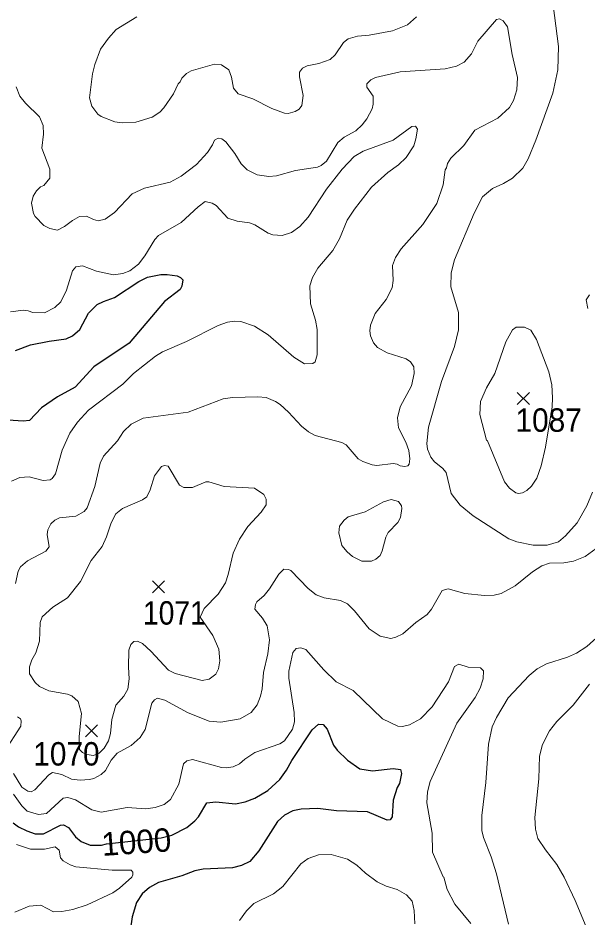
# Model space of a CAD drawing. Extents: x 265 to 291.4, y 7731.5 to 7759.6.
# Drawn here: x 276.962 to 278.902, y 7743.215 to 7746.284 of the extents above; entities that cross this region are included whole.
import ezdxf
from ezdxf.enums import TextEntityAlignment as Align

# ---------------------------------------------------------------- set-up
doc = ezdxf.new("R2010")
doc.units = 0
doc.header["$LTSCALE"] = 0.032
for name, color, linetype, lineweight in [('1', 7, 'Continuous', 25), ('2', 7, 'Continuous', 13), ('21', 7, 'Continuous', 25), ('61', 7, 'Continuous', 13)]:
    doc.layers.add(name, color=color, linetype=linetype, lineweight=lineweight)

msp = doc.modelspace()

# ---------------------------------------------------------------- linework, layer by layer
at = {"layer": '1'}
for points in [[(276.9536, 7745.1492), (277.0046, 7745.1675), (277.0682, 7745.181), (277.1255, 7745.189), (277.1477, 7745.1985), (277.1724, 7745.22), (277.2026, 7745.2765), (277.232, 7745.3051), (277.2535, 7745.3163), (277.2909, 7745.3298), (277.3737, 7745.3847), (277.4039, 7745.399), (277.4484, 7745.4086), (277.4707, 7745.4086), (277.5041, 7745.403), (277.516, 7745.3982), (277.524, 7745.3895), (277.5208, 7745.368), (277.5144, 7745.3569), (277.4612, 7745.3155), (277.341, 7745.1739), (277.2209, 7745.0927), (277.1565, 7745.0235), (277.0968, 7744.9909), (277.0419, 7744.9535), (277.0014, 7744.9098), (276.9791, 7744.9074), (276.9282, 7744.9106)], [(276.9457, 7743.536), (276.9632, 7743.5233), (276.9918, 7743.5089), (277.0205, 7743.4994), (277.0491, 7743.4994), (277.1071, 7743.5289), (277.1164, 7743.5296), (277.1343, 7743.5209), (277.1582, 7743.4884), (277.1772, 7743.4723), (277.2082, 7743.4604), (277.2464, 7743.4604), (277.2631, 7743.4644), (277.4494, 7743.485), (277.4859, 7743.4943), (277.5375, 7743.5209), (277.5646, 7743.5431), (277.5773, 7743.5575), (277.6059, 7743.6052), (277.6362, 7743.6076), (277.703, 7743.6012), (277.7364, 7743.6084), (277.7698, 7743.6203), (277.8135, 7743.6466), (277.8541, 7743.6847), (277.8772, 7743.7158), (277.8955, 7743.7492), (277.9647, 7743.8542), (277.9862, 7743.8733), (278.0021, 7743.8725), (278.0156, 7743.8566), (278.0371, 7743.8017), (278.0498, 7743.7842), (278.0848, 7743.75), (278.127, 7743.7205), (278.1707, 7743.7142), (278.2407, 7743.7221), (278.2662, 7743.7182), (278.2693, 7743.7046), (278.263, 7743.6704), (278.255, 7743.6569), (278.2415, 7743.614), (278.2375, 7743.5567), (278.2312, 7743.5463), (278.2208, 7743.5455), (278.1532, 7743.5742), (278.0482, 7743.5773), (277.9846, 7743.5853), (277.9273, 7743.5829), (277.8987, 7743.5773), (277.87, 7743.5622), (277.8462, 7743.5407), (277.7833, 7743.4405), (277.7523, 7743.4047), (277.7237, 7743.3912), (277.6934, 7743.3832)], [(277.6934, 7743.3832), (277.5932, 7743.3785), (277.5646, 7743.3721), (277.52, 7743.3554), (277.4405, 7743.3323), (277.4103, 7743.3156), (277.3848, 7743.2942)], [(277.3848, 7743.2942), (277.3657, 7743.264), (277.3514, 7743.2162), (277.3442, 7743.1685), (277.3323, 7743.1239), (277.3092, 7743.0889), (277.2909, 7743.077), (277.2368, 7743.0531), (277.2058, 7743.0332), (277.2002, 7743.0253), (277.1931, 7743.003), (277.1931, 7742.9927), (277.2137, 7742.9458), (277.2814, 7742.8503), (277.3354, 7742.7556), (277.3689, 7742.7174), (277.3562, 7742.6944), (277.3259, 7742.692), (277.283, 7742.6944), (277.143, 7742.7333), (277.0427, 7742.7556), (276.9998, 7742.762), (276.9711, 7742.7628), (276.9234, 7742.758)]]:
    msp.add_lwpolyline(points, dxfattribs=at)
at = {"layer": '2'}
for points in [[(278.4635, 7745.2193), (278.4635, 7745.2789), (278.4372, 7745.3656), (278.4388, 7745.4134), (278.4507, 7745.4579), (278.5168, 7745.617), (278.5462, 7745.6727), (278.5796, 7745.7021), (278.6178, 7745.7188), (278.648, 7745.7363), (278.683, 7745.7713), (278.7013, 7745.8031), (278.7276, 7745.8668), (278.7856, 7746.0275), (278.8031, 7746.107), (278.8047, 7746.1866), (278.7817, 7746.3632)], [(278.3211, 7746.2876), (278.2901, 7746.2605), (278.2391, 7746.2398), (278.1596, 7746.2247), (278.1198, 7746.2216), (278.088, 7746.2128), (278.0721, 7746.2001), (278.0434, 7746.1579), (278.026, 7746.142), (277.9878, 7746.1277), (277.948, 7746.1205), (277.9321, 7746.1126), (277.9217, 7746.0991), (277.9217, 7746.0831), (277.9345, 7746.0195), (277.9297, 7745.9845), (277.921, 7745.9726), (277.9066, 7745.9646), (277.8828, 7745.9575), (277.8708, 7745.959), (277.8271, 7745.975), (277.7626, 7746.0076), (277.7125, 7746.0251), (277.6966, 7746.0442), (277.6895, 7746.0816), (277.6807, 7746.1062), (277.6553, 7746.1237), (277.6314, 7746.1261), (277.5518, 7746.103), (277.5367, 7746.0943), (277.5208, 7746.0784), (277.5152, 7746.0656), (277.5081, 7746.0593), (277.4922, 7746.0243), (277.4596, 7745.9766), (277.4453, 7745.9622), (277.419, 7745.9447), (277.3641, 7745.928), (277.3164, 7745.9256), (277.2925, 7745.9288), (277.2448, 7745.9471), (277.2344, 7745.9551), (277.2138, 7745.9829), (277.2058, 7746.0116), (277.2153, 7746.0927), (277.2233, 7746.1245), (277.2432, 7746.177), (277.2702, 7746.2152), (277.2965, 7746.2438), (277.3673, 7746.2876)], [(277.7006, 7745.8214), (277.7229, 7745.7856), (277.7428, 7745.7649), (277.7778, 7745.7482), (277.8175, 7745.7427), (277.843, 7745.7451), (277.9082, 7745.7626), (277.983, 7745.7745), (277.9957, 7745.7801), (278.0132, 7745.7952), (278.0522, 7745.8588), (278.0745, 7745.8771), (278.1135, 7745.8986), (278.1349, 7745.9185), (278.1508, 7745.9392), (278.1691, 7745.9734), (278.1731, 7745.9893), (278.1731, 7746.0171), (278.1508, 7746.0473), (278.1508, 7746.0593), (278.1644, 7746.072), (278.1803, 7746.0807), (278.2646, 7746.0998), (278.4189, 7746.1102), (278.4571, 7746.1189), (278.4826, 7746.1333), (278.508, 7746.1611), (278.5295, 7746.2041), (278.5939, 7746.278), (278.6035, 7746.2804), (278.6162, 7746.274), (278.6305, 7746.2534), (278.6464, 7746.1595), (278.6647, 7746.08), (278.6623, 7746.0386), (278.6512, 7746.002), (278.6377, 7745.9781), (278.5979, 7745.9415), (278.5192, 7745.9002), (278.4817, 7745.8485), (278.4372, 7745.8055), (278.4261, 7745.7872), (278.4229, 7745.7721), (278.4181, 7745.7649), (278.411, 7745.714), (278.3895, 7745.6504), (278.3425, 7745.5788), (278.2686, 7745.4953), (278.2495, 7745.4659), (278.2391, 7745.4388), (278.2407, 7745.3879), (278.2375, 7745.3624), (278.2169, 7745.3227), (278.1795, 7745.2749), (278.1636, 7745.2352), (278.1612, 7745.2161), (278.1636, 7745.1986), (278.1739, 7745.1747), (278.1874, 7745.1588), (278.2201, 7745.1405), (278.2853, 7745.1198), (278.2996, 7745.1102), (278.3115, 7745.0928), (278.3131, 7745.0697), (278.3036, 7745.0283), (278.2654, 7744.9567), (278.2558, 7744.9186), (278.259, 7744.8851), (278.2845, 7744.8358), (278.294, 7744.8072), (278.298, 7744.7786), (278.2956, 7744.7603), (278.2916, 7744.7555), (278.2805, 7744.7531), (278.2646, 7744.7547), (278.255, 7744.7602), (278.2407, 7744.7626), (278.1851, 7744.7563), (278.1691, 7744.7579), (278.1373, 7744.7698), (278.1222, 7744.7793), (278.0808, 7744.8263), (278.0665, 7744.835), (277.975, 7744.8589), (277.952, 7744.8708), (277.9281, 7744.8907), (277.8843, 7744.9384), (277.8557, 7744.9647), (277.8398, 7744.975), (277.808, 7744.9878), (277.7794, 7744.9909), (277.6934, 7744.9878), (277.6616, 7744.9838), (277.5423, 7744.9384), (277.388, 7744.9177)], [(276.9552, 7746.0481), (276.9679, 7746.0163), (276.9878, 7745.9925), (277.0348, 7745.9463), (277.0475, 7745.9161), (277.0491, 7745.8875), (277.0435, 7745.8397), (277.0698, 7745.7681), (277.0698, 7745.7363), (277.0499, 7745.7117), (277.0388, 7745.7069), (277.0252, 7745.6941), (277.0133, 7745.6759), (277.0077, 7745.652), (277.0149, 7745.6162), (277.0205, 7745.6059), (277.0499, 7745.5748), (277.0698, 7745.5645), (277.0968, 7745.5597), (277.1207, 7745.5716), (277.1477, 7745.5923), (277.1716, 7745.6058), (277.1955, 7745.6074), (277.2193, 7745.5955), (277.2352, 7745.5915), (277.2591, 7745.5971), (277.2909, 7745.6202), (277.3514, 7745.6838), (277.3928, 7745.7029), (277.4803, 7745.7228), (277.5184, 7745.7435), (277.5709, 7745.7832), (277.6083, 7745.8246)], [(276.9393, 7744.703), (276.968, 7744.7157), (276.9998, 7744.7173), (277.0475, 7744.7054), (277.0714, 7744.707), (277.0785, 7744.7117), (277.0897, 7744.7276), (277.1119, 7744.8088), (277.139, 7744.8661), (277.1644, 7744.9042), (277.2018, 7744.9448), (277.3188, 7745.0339), (277.3561, 7745.0705), (277.4309, 7745.1293), (277.4548, 7745.1437), (277.5359, 7745.1795), (277.6441, 7745.2344), (277.6759, 7745.2455), (277.6998, 7745.2487), (277.7221, 7745.2471), (277.7682, 7745.2312), (277.8151, 7745.2025), (277.9018, 7745.1254), (277.9385, 7745.1031), (277.9671, 7745.1039), (277.975, 7745.1095), (277.9814, 7745.1333), (277.9814, 7745.2208), (277.9758, 7745.2527), (277.9591, 7745.3083), (277.9567, 7745.3688), (277.9663, 7745.3974), (277.9846, 7745.4293), (278.0355, 7745.4897), (278.0578, 7745.5295), (278.084, 7745.5931), (278.1087, 7745.6313), (278.1675, 7745.7061), (278.2224, 7745.7562), (278.2598, 7745.7824), (278.2853, 7745.8079), (278.3115, 7745.8477), (278.3187, 7745.8715), (278.3235, 7745.9042), (278.3171, 7745.9145), (278.3044, 7745.9137), (278.2407, 7745.866), (278.1389, 7745.8294), (278.1079, 7745.8103), (278.0673, 7745.7681), (278.0132, 7745.6997), (277.9512, 7745.6043), (277.9225, 7745.5724), (277.8939, 7745.551), (277.8621, 7745.5414), (277.8303, 7745.543), (277.8144, 7745.5494), (277.7698, 7745.578), (277.7507, 7745.5844), (277.7094, 7745.5899), (277.6775, 7745.6003), (277.6378, 7745.6432), (277.6242, 7745.6512), (277.6004, 7745.6568), (277.5757, 7745.6392), (277.5184, 7745.5852), (277.4405, 7745.5406), (277.4278, 7745.5279), (277.3943, 7745.4722), (277.3721, 7745.4436), (277.3434, 7745.4205), (277.3196, 7745.411), (277.2877, 7745.407), (277.2289, 7745.4197), (277.1812, 7745.4372), (277.1589, 7745.434), (277.1477, 7745.4205), (277.127, 7745.3545), (277.108, 7745.3147), (277.0873, 7745.2956), (277.0523, 7745.2773), (277.0125, 7745.2781), (276.9966, 7745.2845), (276.9807, 7745.2861), (276.9361, 7745.2805)], [(277.6083, 7745.8246), (277.625, 7745.8509), (277.6314, 7745.8668), (277.6441, 7745.8731), (277.6569, 7745.8707), (277.6704, 7745.8604), (277.7006, 7745.8214)], [(278.9105, 7745.3386), (278.8994, 7745.3219), (278.905, 7745.2924)], [(278.3696, 7744.7841), (278.3585, 7744.812), (278.3561, 7744.8311), (278.3616, 7744.8867), (278.4054, 7745.0427), (278.4507, 7745.162), (278.4635, 7745.2193)], [(277.388, 7744.9177), (277.3482, 7744.8971), (277.3219, 7744.8724), (277.3005, 7744.8406), (277.2535, 7744.7881), (277.2424, 7744.7642), (277.2241, 7744.6847)], [(278.9209, 7744.6656), (278.901, 7744.6179), (278.8684, 7744.5606), (278.8286, 7744.516), (278.8047, 7744.4961), (278.7658, 7744.4842), (278.718, 7744.4842), (278.6623, 7744.4961), (278.6353, 7744.5057), (278.5136, 7744.5844), (278.469, 7744.6202), (278.4388, 7744.6608), (278.4213, 7744.7324), (278.4094, 7744.7475), (278.3823, 7744.769), (278.3696, 7744.7841)], [(277.2241, 7744.6847), (277.1971, 7744.6115), (277.1875, 7744.5995), (277.1589, 7744.5828), (277.1032, 7744.5773), (277.0873, 7744.5693), (277.0738, 7744.5566), (277.0634, 7744.5367), (277.061, 7744.5208), (277.0682, 7744.4786), (277.057, 7744.4635), (276.9942, 7744.4309), (276.9703, 7744.4102), (276.9624, 7744.3959), (276.9528, 7744.3538)], [(278.586, 7744.314), (278.6098, 7744.3195), (278.6576, 7744.345), (278.7164, 7744.3935), (278.7482, 7744.4142), (278.7737, 7744.423), (278.823, 7744.4237), (278.8564, 7744.4293), (278.8962, 7744.446), (278.9837, 7744.5097)], [(276.9465, 7743.7054), (276.9743, 7743.6585), (276.995, 7743.645), (277.0069, 7743.6426), (277.0189, 7743.6489), (277.0666, 7743.6999), (277.0793, 7743.7078), (277.1112, 7743.7015), (277.1446, 7743.6855), (277.1732, 7743.6824), (277.205, 7743.684), (277.2209, 7743.6879), (277.2448, 7743.7014), (277.2599, 7743.715), (277.2798, 7743.7508), (277.2997, 7743.7739), (277.3482, 7743.8009), (277.3784, 7743.8279), (277.3951, 7743.855), (277.4182, 7743.9449), (277.4269, 7743.9568), (277.4373, 7743.9624), (277.4628, 7743.9552), (277.5423, 7743.9123), (277.6139, 7743.8836), (277.6537, 7743.8796), (277.7189, 7743.8916), (277.7571, 7743.913), (277.7777, 7743.9393), (277.7889, 7743.9688), (277.7945, 7743.9942), (277.7992, 7744.0499), (277.8135, 7744.1135), (277.8199, 7744.1613), (277.8112, 7744.209), (277.796, 7744.2352), (277.7698, 7744.2655), (277.7714, 7744.2822), (277.7762, 7744.2909), (277.8008, 7744.3124), (277.8199, 7744.3355), (277.8517, 7744.3856), (277.8677, 7744.4023), (277.8844, 7744.4015), (277.8923, 7744.3975), (277.9512, 7744.3363), (277.9782, 7744.3148), (278.0053, 7744.3044), (278.061, 7744.2957), (278.0848, 7744.2845), (278.1095, 7744.2599), (278.1588, 7744.1986), (278.1962, 7744.174), (278.2328, 7744.166), (278.2503, 7744.17), (278.2741, 7744.1811), (278.3179, 7744.2201), (278.3569, 7744.2479)], [(278.3569, 7744.2479), (278.372, 7744.2663), (278.4086, 7744.3299), (278.4285, 7744.3355), (278.4857, 7744.3195), (278.5526, 7744.3124), (278.586, 7744.314)], [(278.9455, 7744.1779), (278.901, 7744.1382), (278.866, 7744.1159), (278.8358, 7744.1024), (278.7642, 7744.0793), (278.7323, 7744.0618), (278.7045, 7744.0395), (278.6337, 7743.9632), (278.5931, 7743.8956), (278.5788, 7743.8637), (278.5661, 7743.8049), (278.5573, 7743.6744), (278.5438, 7743.5615), (278.5438, 7743.5106), (278.5494, 7743.4867), (278.5756, 7743.4199), (278.5939, 7743.3626), (278.6345, 7743.1908)], [(278.5064, 7743.1924), (278.4515, 7743.2584), (278.4253, 7743.3085), (278.4141, 7743.3506), (278.411, 7743.3522), (278.3752, 7743.4358), (278.3736, 7743.501), (278.3553, 7743.6044), (278.3585, 7743.6426), (278.3672, 7743.6776), (278.4587, 7743.8765), (278.5207, 7743.964), (278.5382, 7743.9958), (278.5478, 7744.0276), (278.5494, 7744.0554), (278.539, 7744.0658), (278.4969, 7744.0674), (278.4651, 7744.0785), (278.4507, 7744.0706), (278.4293, 7744.0181), (278.3744, 7743.9322), (278.3346, 7743.8916), (278.2964, 7743.8709), (278.2726, 7743.8653), (278.2566, 7743.8661), (278.2049, 7743.8916), (278.1047, 7743.9878), (278.0466, 7744.0173), (278.0045, 7744.0586), (277.9432, 7744.1286), (277.9257, 7744.1342), (277.9098, 7744.1318), (277.8987, 7744.1183), (277.8851, 7744.0547), (277.8851, 7744.0308), (277.9034, 7743.9131), (277.9042, 7743.8812), (277.8979, 7743.8566), (277.87, 7743.8168)], [(278.8986, 7743.1812), (278.862, 7743.2719), (278.8246, 7743.3515), (278.7992, 7743.3944), (278.7602, 7743.4445), (278.7347, 7743.4835), (278.7268, 7743.5153), (278.7244, 7743.5551), (278.7379, 7743.6871), (278.7403, 7743.7635), (278.7498, 7743.8033), (278.7745, 7743.851), (278.7992, 7743.8828), (278.8548, 7743.9385), (278.9105, 7744.0101)], [(276.96, 7743.8987), (276.9703, 7743.8916), (276.9727, 7743.8844), (276.9711, 7743.8661), (276.9162, 7743.7794)], [(277.87, 7743.8168), (277.8541, 7743.8065), (277.7698, 7743.777), (277.7348, 7743.754), (277.7173, 7743.7381), (277.695, 7743.7277), (277.6712, 7743.7237)], [(277.6712, 7743.7237), (277.6553, 7743.7253), (277.5566, 7743.7524), (277.5375, 7743.7484), (277.5256, 7743.738), (277.5097, 7743.6681), (277.4818, 7743.6156), (277.4604, 7743.5996), (277.4293, 7743.5893), (277.3975, 7743.5837), (277.3339, 7743.5885), (277.2448, 7743.5726), (277.213, 7743.5813), (277.1581, 7743.6147), (277.1318, 7743.6235), (277.1159, 7743.6203), (277.0586, 7743.5686), (277.0316, 7743.5646), (276.9934, 7743.5766), (276.9743, 7743.5949), (276.9465, 7743.6346)], [(276.9568, 7743.4628), (277.0046, 7743.4461), (277.0523, 7743.4469), (277.0889, 7743.4548), (277.1016, 7743.4429), (277.1064, 7743.4175), (277.1159, 7743.4063), (277.1398, 7743.3928), (277.1589, 7743.3864), (277.283, 7743.3753), (277.3482, 7743.3745), (277.3538, 7743.3682), (277.3538, 7743.3586), (277.3498, 7743.3507), (277.3084, 7743.3133), (277.2846, 7743.2973), (277.1971, 7743.2568), (277.1493, 7743.2409), (277.1112, 7743.2337), (277.0825, 7743.2329), (277.0396, 7743.2552), (276.9998, 7743.252), (276.9505, 7743.2321)], [(277.7165, 7743.2027), (277.7404, 7743.2361), (277.7658, 7743.2616), (277.8335, 7743.2942), (277.8645, 7743.3196), (277.9257, 7743.3968), (277.9512, 7743.4151), (277.9862, 7743.427), (278.0291, 7743.4286), (278.0848, 7743.4127), (278.1166, 7743.392), (278.1469, 7743.3642), (278.1866, 7743.3355), (278.2169, 7743.3204), (278.2551, 7743.3093), (278.2869, 7743.2902), (278.306, 7743.2687), (278.3131, 7743.2369), (278.3155, 7743.1915)]]:
    msp.add_lwpolyline(points, dxfattribs=at)
for points in [[(278.5627, 7744.8405), (278.5589, 7744.8422), (278.5366, 7744.9297), (278.539, 7744.9742), (278.5597, 7745.0212), (278.5876, 7745.0705), (278.6257, 7745.1787), (278.648, 7745.2193), (278.66, 7745.228), (278.6894, 7745.228), (278.7101, 7745.2176), (278.7299, 7745.1866), (278.7713, 7745.0761), (278.7817, 7745.0315), (278.7848, 7744.987), (278.7832, 7744.9567), (278.7602, 7744.8183), (278.7459, 7744.7547), (278.7307, 7744.7133), (278.7124, 7744.6855), (278.6973, 7744.6711), (278.6822, 7744.6632), (278.6687, 7744.6608), (278.6592, 7744.6632), (278.6377, 7744.6791), (278.6202, 7744.7006)], [(277.5963, 7744.268), (277.583, 7744.2387), (277.6258, 7744.1764), (277.6465, 7744.1294), (277.6505, 7744.0897), (277.6457, 7744.0626), (277.6362, 7744.0435), (277.6139, 7744.0268), (277.59, 7744.0228), (277.4978, 7744.0467), (277.4747, 7744.057), (277.415, 7744.1223), (277.3864, 7744.1485), (277.3689, 7744.1565), (277.3569, 7744.1549), (277.3466, 7744.1453), (277.3402, 7744.1263), (277.3386, 7744.0674), (277.341, 7744.0276), (277.3363, 7743.9926), (277.3227, 7743.9688), (277.2957, 7743.9385), (277.2814, 7743.8892), (277.2774, 7743.8415), (277.2702, 7743.816), (277.2559, 7743.7914), (277.239, 7743.7741), (277.2197, 7743.7662), (277.1965, 7743.7695), (277.1819, 7743.7761), (277.1713, 7743.7867), (277.1699, 7743.8313), (277.1788, 7743.9091), (277.1668, 7743.9504), (277.1453, 7743.9695), (277.1302, 7743.9751), (277.0666, 7743.987), (277.0348, 7744.0014), (277.0205, 7744.0149), (277.0014, 7744.0451), (277.0014, 7744.069), (277.0085, 7744.0928), (277.022, 7744.1167), (277.0348, 7744.1565), (277.0372, 7744.2201), (277.0443, 7744.2392), (277.0801, 7744.2726), (277.1302, 7744.3044), (277.1748, 7744.3601), (277.2114, 7744.4317), (277.2488, 7744.4795), (277.2639, 7744.5129), (277.2798, 7744.5606), (277.2957, 7744.5916), (277.318, 7744.6099), (277.3864, 7744.6385), (277.4015, 7744.6489), (277.4126, 7744.6735), (277.4277, 7744.7213), (277.4508, 7744.7523), (277.4612, 7744.7563), (277.4739, 7744.7539), (277.5129, 7744.6887), (277.5272, 7744.6807), (277.5566, 7744.6815), (277.6028, 7744.7006), (277.6123, 7744.7006), (277.6648, 7744.6847), (277.7682, 7744.6791), (277.8, 7744.6576), (277.808, 7744.6417), (277.808, 7744.6218), (277.7905, 7744.5972), (277.7459, 7744.5479), (277.7165, 7744.5049), (277.695, 7744.4572), (277.6783, 7744.384), (277.6688, 7744.3554), (277.6441, 7744.3172)], [(278.208, 7744.6319), (278.1453, 7744.598), (278.088, 7744.5813), (278.0737, 7744.5701), (278.0586, 7744.5487), (278.0554, 7744.5264), (278.0665, 7744.4834), (278.084, 7744.4612), (278.1023, 7744.4452), (278.1341, 7744.4293), (278.1676, 7744.4301), (278.1819, 7744.4365), (278.1962, 7744.4484), (278.2041, 7744.4651), (278.2161, 7744.5113), (278.224, 7744.5272), (278.2566, 7744.5614), (278.2662, 7744.5781), (278.271, 7744.6099), (278.2694, 7744.6179), (278.259, 7744.6338), (278.2344, 7744.6401)]]:
    msp.add_lwpolyline(points, close=True, dxfattribs=at)
at = {"layer": '21'}
for p, q in [((278.6644, 7745.0055), (278.7056, 7744.9643)), ((278.7056, 7745.0055), (278.6644, 7744.9643)), ((277.4204, 7744.3622), (277.4616, 7744.321)), ((277.4616, 7744.3622), (277.4204, 7744.321)), ((277.1914, 7743.8708), (277.2326, 7743.8296)), ((277.2326, 7743.8708), (277.1914, 7743.8296))]:
    msp.add_line(p, q, dxfattribs=at)

# ---------------------------------------------------------------- texts
at = {"layer": '61'}
for s, width, p in [('1087', 0.95, (278.7713, 7744.8712)), ('1071', 0.9, (277.495, 7744.213)), ('1070', 0.95, (277.1269, 7743.732))]:
    msp.add_text(s, height=0.08, dxfattribs=dict(at, width=width)).set_placement(p, align=Align.CENTER)
msp.add_text('1000', height=0.08, rotation=3.933, dxfattribs=at).set_placement((277.368, 7743.4315), align=Align.CENTER)

doc.saveas('drawing.dxf')
